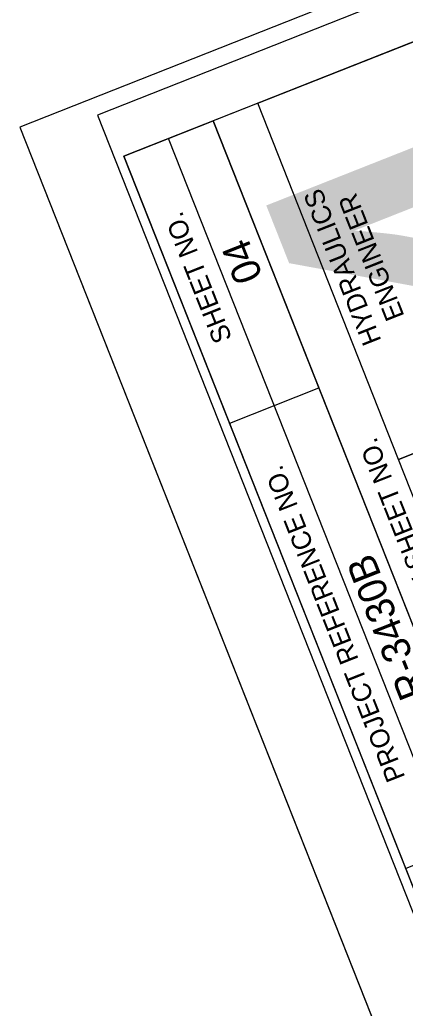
# Model space of a CAD drawing. Extents: x 1250793 to 1252430, y 745882 to 747850.
# Drawn here: x 1250792.7 to 1250893.3, y 747217.3 to 747475.4 of the extents above; entities that cross this region are included whole.
import ezdxf

# ---------------------------------------------------------------- set-up
doc = ezdxf.new("R2010")
doc.units = 0
for name, color, linetype in [('Sheet Cutting Line CELL', 7, 'Continuous'), ('Sheet Data Field CELL', 7, 'Continuous'), ('Sheet Plan CELL', 7, 'Continuous'), ('Sheet Plan Layout CELL', 7, 'Continuous'), ('Sheet Plot Border Inside CELL', 7, 'Continuous'), ('Sheet Plot Border Outside CELL', 7, 'Continuous')]:
    doc.layers.add(name, color=color, linetype=linetype)

msp = doc.modelspace()

# ---------------------------------------------------------------- linework, layer by layer
at = {"layer": 'Sheet Cutting Line CELL'}
msp.add_line((1250792.68, 747447.34), (1251411.72, 745881.79), dxfattribs=at)
at = {"layer": 'Sheet Plan CELL'}
for p, q in [((1250916.72, 747262.99), (1250843.14, 747449)), ((1250916.72, 747262.99), (1250843.14, 747449)), ((1250905.07, 747258.37), (1250831.52, 747444.41)), ((1250891.55, 747360.62), (1250996.12, 747401.99)), ((1250847.49, 747370.05), (1250870.72, 747379.29))]:
    msp.add_line(p, q, dxfattribs=at)
for points in [[(1250819.83, 747439.83), (1251371.41, 746044.88), (1252347.85, 746430.97), (1251796.28, 747825.9)], [(1250891.55, 747360.62), (1250854.77, 747453.6), (1250959.39, 747494.98), (1250996.18, 747401.99)], [(1250893.39, 747253.76), (1250819.83, 747439.83), (1250843.14, 747449), (1250916.72, 747262.99)], [(1250928.33, 747267.58), (1250891.55, 747360.62), (1250996.18, 747401.99), (1251032.94, 747308.96)]]:
    msp.add_lwpolyline(points, close=True, dxfattribs=at)
at = {"layer": 'Sheet Plan Layout CELL'}
msp.add_lwpolyline([(1251104.49, 747295.07), (1251016.51, 747517.58), (1250819.83, 747439.84), (1250907.82, 747217.3)], close=True, dxfattribs=at)
at = {"layer": 'Sheet Plot Border Inside CELL'}
msp.add_lwpolyline([(1252406.62, 746289.16), (1251794.01, 747838.43), (1250812.93, 747450.51), (1251425.54, 745901.23)], close=True, dxfattribs=at)
at = {"layer": 'Sheet Plot Border Outside CELL'}
msp.add_lwpolyline([(1252430, 746284.43), (1251810.97, 747849.98), (1250792.68, 747447.34), (1251411.72, 745881.79)], close=True, dxfattribs=at)

# ---------------------------------------------------------------- texts
at = {"layer": 'Sheet Data Field CELL'}
for s, p in [('04', (1250856.19, 747408.39)), ('R-3430B', (1250899.24, 747299.7))]:
    msp.add_text(s, height=7.5, rotation=111.5744, dxfattribs=at).set_placement(p)
at = {"layer": 'Sheet Plan CELL'}
for s, height, p in [('HYDRAULICS', 5, (1250887.11, 747391.63)), ('ENGINEER', 5, (1250893.13, 747398.05)), ('SHEET NO.', 5, (1250848.16, 747392.19)), ('R/W SHEET NO.', 5.0001, (1250904.31, 747319.37)), ('PROJECT REFERENCE NO.', 5.0001, (1250893.34, 747277.62))]:
    msp.add_text(s, height=height, rotation=111.5744, dxfattribs=at).set_placement(p)
at = {"layer": 'Sheet Plan Layout CELL'}
msp.add_text('04', height=131.25, rotation=111.5743, dxfattribs=at).set_placement((1251042.72, 747314.2))

doc.saveas('drawing.dxf')
